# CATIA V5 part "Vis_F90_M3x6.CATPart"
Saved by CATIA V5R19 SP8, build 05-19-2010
Part number: Vis F90 M3x6
Publications: "Mating Edge", "Axis"
Bounding box of the stored display mesh (mm): x -6.29 to 0, y -2.999 to 2.999, z -2.999 to 2.999
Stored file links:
  D:\Documents\1_Travail\1 - ac-limoges.fr\ac-limoges.fr\Emmanuel Maynard - STI2D_Turgot\1 - IT-I2D\Activités_IT_Première\IT_3_Abris_bus\Maquettes numériques\Abribus_eleve\Vis_F90_M3x6.CATPart
  C:\Program Files\Dassault Systemes\B19\win_b64\startup\components\MechanicalStandardParts\EN_Standards\Design_Tables\EN_ISO_10642_HEXAGON_SOCKET_COUNTERSUNK_SCREW.txt
  C:\Program Files\Dassault Systemes\B19\win_b64\startup\components\MechanicalStandardParts\ISO_Standards\Design_Tables\ISO_10642_HEXAGON_SOCKET_COUNTERSUNK_SCREW.txt
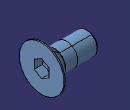
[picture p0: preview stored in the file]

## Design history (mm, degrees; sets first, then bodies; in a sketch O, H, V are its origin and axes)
Parameters
  l_length_nom = 8 mm
  b_ref = 18
  l_length_min = 7.71 mm
  l_length_max = 8.29 mm
  dk_head_dia_max = 6.72 mm
  dk_head_dia_min = 5.54 mm
  ls = 3.36 mm
  k_hed_depth = 1.86 mm
  r = 0.1 mm
  s_across_flats = 2 mm
  t_insert_depth = 1.1 mm
  d_dia = 3 mm
  threading = 4.64 mm
  p_pitch = 0.5 mm
Body1 "PartBody" (main body)
  Sketch1 on zx-plane, origin (0, 0, 0), H (-1, 0, 0), V (0, 0, 1)
    line L1 (0, 3) -> (0.1667, 3)
    point P2 (0.1667, 3)
    line L2 (0.1667, 3) -> (1.6667, 1.5)
    line L3 (1.6667, 1.5) -> (3.36, 1.5)
    line L4 (3.36, 1.5) -> (3.36, 1.4634)
    point P5 (3.36, 1.4634)
    line L5 (3.36, 1.4634) -> (6.0194, 1.4634)
    point P6 (6.0194, 1.4634)
    line L6 (6.0193, 1.4634) -> (6.29, 1.1928)
    axis line L7 (-30, 0) -> (125, 0)
    line L8 (6.29, 1.1928) -> (6.29, 0)
    point P10 (6.29, 0)
    line L9 (0, 3) -> (0, 0)
    distance L9 P5 = 3.36 {= ls}
    distance L9 L8 = 6.29
    angle L5 L6 = 45
    distance L5 L7 = 1.4634 {= d_dia /2.05}
    distance L3 L7 = 1.5 {= d_dia  /2}
    angle L7 L2 = 45
    distance L1 L7 = 3
    distance L9 P2 = 0.1667 {= p_pitch /3}
    distance P6 L8 = 0.2707 {= p_pitch *0.5413}
    horizontal: L1 H, L3 H, L5 H, L7 H
    vertical: L4 V, L9 V
    fix: L7
    coincidence: P10 L7
  Shaft1: profile Sketch1, axis Sketch1.L7, angle 360
  Body2
    Sketch2 on face of Shaft1, origin (0, 0, 0), H (0, 1, 0), V (0, 0, 1)
      point P1 (1, -0.5774)
      point P2 (1, 0.5774)
      point P3 (0, 1.1547)
      point P4 (-1, 0.5774)
      point P5 (-1, -0.5774)
      point P6 (0, -1.1547)
      point P7 (1, 0)
      line L1 (1, -0.5774) -> (1, 0.5774)
      line L2 (1, 0.5774) -> (0, 1.1547)
      line L3 (0, 1.1547) -> (-1, 0.5774)
      line L4 (-1, 0.5774) -> (-1, -0.5774)
      line L5 (-1, -0.5774) -> (0, -1.1547)
      line L6 (0, -1.1547) -> (1, -0.5774)
      construction line L7 (0, 0) -> (1, 0)
      construction circle A1 centre (0, 0) radius 1.1547
      construction arc A2 centre (-1, -0.5774) radius 1.1547 from (-1, 0.5774) to (0, -1.1547) cw
      construction arc A3 centre (1, 0.5774) radius 1.1547 from (0, 1.1547) to (1, -0.5774) ccw
      point P8 (-1, -0.5774)
      point P9 (1, 0.5774)
      distance L1 L4 = 2 {= s_across_flats}
      horizontal: L7 H
      coincidence: A1 P1, A1 P2, A1 P3, A1 P4, A1 P5, A1 P6, A2 P4, A2 P6, A2 O, P8 P5, A3 P3, A3 P1, A3 O, P9 P2
      midpoint: P7 L1
    Pad1: profile Sketch2, direction (-1, 0, 0), length 20
    Body3
      Sketch3 on zx-plane, origin (0, 0, 0), H (-1, 0, 0), V (0, 0, 1)
        line L1 (0, 0) -> (0, 1.1547)
        line L2 (0, 1.1547) -> (1.1, 1.1547)
        point P2 (1.1, 1.1547)
        line L3 (1.1, 1.1547) -> (1.7667, 0)
        point P3 (1.7667, 0)
        axis line L4 (-13.9938, 0) -> (46.4324, 0)
        reference projected line E1 (0, 1.1547) -> (20, 1.1547) from edge [face of Pad1 | face of Pad1]
        angle L3 L4 = 60
        distance L1 P2 = 1.1 {= t_insert_depth}
        vertical: L1 V
        horizontal: L2 H, L4 H
        fix: L4
        coincidence: L2 E1, P3 L4
      Shaft2: profile Sketch3, axis Sketch3.L4, angle 360
    Intersect1: tool Body3
  Remove1: tool Body2
  Fillet1: radius 0.1 {= r}, on edge [face of Shaft1 | face of Shaft1]
  Thread1: diameter 2.9268 {= d_dia /1.025}, depth 4.64 {= threading}, pitch 1, on face of Shaft1, from face of Shaft1 from Sketch1.L4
